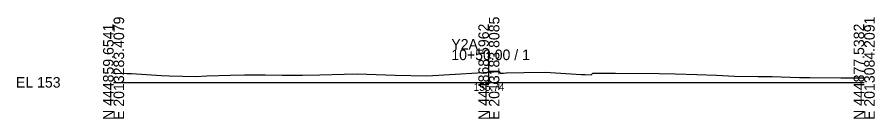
# Model space of a CAD drawing. Extents: x -26 to 203, y -10 to 5517.
# Drawn here: x -25.7 to 202.8, y 990.3 to 1017.3 of the extents above; entities that cross this region are included whole.
import ezdxf

# ---------------------------------------------------------------- set-up
doc = ezdxf.new("R2010")
doc.units = 0
for name, color, linetype in [('Default', 7, 'Continuous'), ('Exist Cross Section Cell', 7, 'Continuous'), ('Exist XS Center Line Elevation Label', 7, 'Continuous'), ('Exist XS Ground Line', 7, 'Continuous')]:
    doc.layers.add(name, color=color, linetype=linetype)

msp = doc.modelspace()

# ---------------------------------------------------------------- linework, layer by layer
at = {"layer": 'Exist Cross Section Cell'}
for p, q in [((100, 1000), (100, 1008.72)), ((0, 1000), (100, 1000)), ((100, 1000), (200, 1000))]:
    msp.add_line(p, q, dxfattribs=at)
at = {"layer": 'Exist XS Ground Line'}
msp.add_lwpolyline([(0, 1002.44), (3.53, 1002.35), (4.76, 1002.32), (12.74, 1001.86), (14.81, 1001.71), (21.95, 1001.59), (24.85, 1001.71), (31.17, 1001.93), (34.89, 1001.96), (40.38, 1001.98), (44.93, 1001.95), (50.38, 1001.95), (54.97, 1002.04), (61.41, 1002.22), (65.01, 1002.23), (72.44, 1002.03), (75.05, 1001.9), (83.47, 1001.76), (85.1, 1001.81), (87.98, 1001.97), (100, 1002.74), (102.62, 1002.91), (103.04, 1002.41), (103.87, 1002.46), (104.62, 1002.51), (109.32, 1002.61), (114.96, 1002.72), (124.65, 1002.11), (125.69, 1002.06), (127.27, 1001.96), (127.69, 1002.46), (132.7, 1002.45), (133.74, 1002.42), (145.34, 1002.34), (149.66, 1002.26), (155.39, 1002.06), (160.69, 1001.87), (165.43, 1001.61), (171.73, 1001.55), (175.47, 1001.52), (182.76, 1001.32), (185.51, 1001.29), (193.79, 1001.23), (195.55, 1001.24), (200, 1001.2)], dxfattribs=at)

# ---------------------------------------------------------------- texts
at = {"layer": 'Default'}
msp.add_text('-', height=0.0001, dxfattribs=at).set_placement((0, 1000))
at = {"layer": 'Exist Cross Section Cell'}
for s, p in [('E 2013283.4079', (2.8, 990)), ('E 2013183.8085', (102.8, 990)), ('E 2013084.2091', (202.8, 990)), ('N 444859.6541', (0, 990)), ('N 444868.5962', (100, 990)), ('N 444877.5382', (200, 990))]:
    msp.add_text(s, height=2.8, rotation=90, dxfattribs=at).set_placement(p)
for s, p in [('Y2A', (90, 1008.72)), ('10+50.00 / 1', (90, 1005.92)), ('EL 153', (-26, 998.6))]:
    msp.add_text(s, height=2.8, dxfattribs=at).set_placement(p)
at = {"layer": 'Exist XS Center Line Elevation Label'}
msp.add_text('155.74', height=2, dxfattribs=at).set_placement((95.96, 997.74))

doc.saveas('drawing.dxf')
